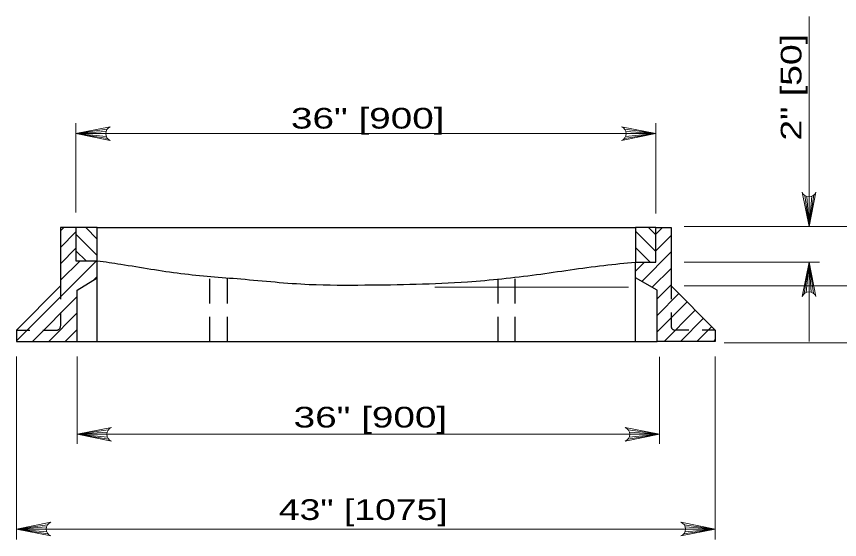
# Model space of a CAD drawing. Extents: x 1083.1 to 1123, y 697.4 to 741.4.
# Drawn here: x 1105.34 to 1111.55, y 704.05 to 708 of the extents above; entities that cross this region are included whole.
import ezdxf

# ---------------------------------------------------------------- set-up
doc = ezdxf.new("R2010")
doc.units = 0
doc.header["$LTSCALE"] = 0.062
doc.linetypes.add('MEDIUM_DASHED', pattern=[4.5, 3, -1.5])
doc.linetypes.add('SHORT_DASHED', pattern=[2.7, 1.5, -1.2])
doc.layers.add('1', color=7, linetype='Continuous', lineweight=13)

msp = doc.modelspace()

# ---------------------------------------------------------------- linework, layer by layer
at = {"layer": '1'}
for p, q in [((1111.32425, 707.99533), (1111.32425, 706.41158)), ((1105.78967, 706.518), (1105.78967, 707.19033)), ((1110.16733, 706.50958), (1110.16733, 707.19033)), ((1106.02425, 707.1445), (1105.78967, 707.11167)), ((1106.01633, 707.12825), (1105.78967, 707.11167)), ((1106.01392, 707.11167), (1105.78967, 707.11167)), ((1106.01808, 707.09058), (1105.78967, 707.11167)), ((1106.027, 707.07533), (1105.78967, 707.11167)), ((1105.78967, 707.11167), (1110.16733, 707.11167)), ((1109.92992, 707.07533), (1110.16733, 707.11167)), ((1109.93275, 707.1445), (1110.16733, 707.11167)), ((1109.93892, 707.09058), (1110.16733, 707.11167)), ((1109.94067, 707.12825), (1110.16733, 707.11167)), ((1109.94308, 707.11167), (1110.16733, 707.11167)), ((1111.29142, 706.64617), (1111.32425, 706.41158)), ((1111.30767, 706.63825), (1111.32425, 706.41158)), ((1111.3605, 706.64892), (1111.32425, 706.41158)), ((1111.34533, 706.64), (1111.32425, 706.41158)), ((1111.32425, 706.63583), (1111.32425, 706.41158)), ((1105.67258, 706.37817), (1105.69808, 706.40367)), ((1105.67258, 706.25392), (1105.78967, 706.371)), ((1105.95067, 706.31642), (1105.86342, 706.40367)), ((1110.16733, 706.22392), (1110.01467, 706.37658)), ((1110.16733, 706.348), (1110.11175, 706.40367)), ((1110.16733, 706.39525), (1110.16733, 706.40367)), ((1110.16733, 706.35233), (1110.21867, 706.40367)), ((1110.16733, 706.39525), (1110.16733, 706.40367)), ((1110.3815, 706.41158), (1112.81892, 706.41158)), ((1105.95067, 706.19233), (1105.78967, 706.35325)), ((1110.16733, 706.22817), (1110.28333, 706.34417)), ((1105.67258, 706.12975), (1105.78967, 706.24683)), ((1110.124, 706.14292), (1110.01467, 706.25233)), ((1105.86542, 706.15333), (1105.78967, 706.229)), ((1110.06075, 705.9975), (1110.28333, 706.22)), ((1105.34017, 705.54908), (1105.94442, 706.15333)), ((1105.67258, 706.00567), (1105.82025, 706.15333)), ((1110.01467, 706.0755), (1110.08208, 706.14292)), ((1111.40292, 706.14292), (1110.3815, 706.14292)), ((1111.288, 705.90558), (1111.32425, 706.14292)), ((1111.30317, 705.91458), (1111.32425, 706.14292)), ((1111.32425, 705.91867), (1111.32425, 706.14292)), ((1111.34083, 705.91625), (1111.32425, 706.14292)), ((1111.35708, 705.90833), (1111.32425, 706.14292)), ((1111.32425, 706.14292), (1111.32425, 705.54517)), ((1110.14025, 705.95275), (1110.28333, 706.09575)), ((1105.92092, 706.00567), (1105.95067, 706.03525)), ((1108.49892, 705.95442), (1109.96083, 705.95442)), ((1110.177, 705.86533), (1110.28333, 705.97158)), ((1105.4605, 705.54517), (1105.79842, 705.88308)), ((1110.177, 705.74117), (1110.34108, 705.90525)), ((1110.177, 705.617), (1110.40317, 705.84308)), ((1105.58467, 705.54517), (1105.79842, 705.759)), ((1110.22925, 705.54517), (1110.46517, 705.781)), ((1110.35358, 705.54517), (1110.52725, 705.719)), ((1105.70883, 705.54517), (1105.79842, 705.63483)), ((1110.47767, 705.54517), (1110.58925, 705.65675)), ((1110.60183, 705.54517), (1110.61625, 705.55958)), ((1112.81892, 705.53383), (1110.68208, 705.53383)), ((1105.34017, 705.43083), (1105.34017, 704.0505)), ((1105.79842, 705.43083), (1105.79842, 704.773)), ((1110.61625, 705.43083), (1110.61625, 704.0505)), ((1110.19408, 705.42825), (1110.19408, 704.773)), ((1106.03308, 704.87717), (1105.79842, 704.84433)), ((1109.9595, 704.87717), (1110.19408, 704.84433)), ((1106.02508, 704.86092), (1105.79842, 704.84433)), ((1106.02267, 704.84433), (1105.79842, 704.84433)), ((1106.02683, 704.82325), (1105.79842, 704.84433)), ((1106.03583, 704.80808), (1105.79842, 704.84433)), ((1105.79842, 704.84433), (1110.19408, 704.84433)), ((1109.95667, 704.80808), (1110.19408, 704.84433)), ((1109.96567, 704.82325), (1110.19408, 704.84433)), ((1109.96742, 704.86092), (1110.19408, 704.84433)), ((1109.96983, 704.84433), (1110.19408, 704.84433)), ((1105.57475, 704.162), (1105.34017, 704.12917)), ((1105.56683, 704.14575), (1105.34017, 704.12917)), ((1105.56442, 704.12917), (1105.34017, 704.12917)), ((1105.56858, 704.10808), (1105.34017, 704.12917)), ((1105.5775, 704.09292), (1105.34017, 704.12917)), ((1105.34017, 704.12917), (1110.61625, 704.12917)), ((1110.37883, 704.09292), (1110.61625, 704.12917)), ((1110.38158, 704.162), (1110.61625, 704.12917)), ((1110.38783, 704.10808), (1110.61625, 704.12917)), ((1110.38958, 704.14575), (1110.61625, 704.12917)), ((1110.392, 704.12917), (1110.61625, 704.12917))]:
    msp.add_line(p, q, dxfattribs=at)
at = {"layer": '1', "lineweight": 25}
for p, q in [((1105.95067, 706.40367), (1110.01467, 706.40367)), ((1105.95067, 705.54267), (1105.95067, 706.02342)), ((1110.01467, 705.54267), (1110.01467, 706.02342)), ((1105.79842, 705.54517), (1110.177, 705.54517))]:
    msp.add_line(p, q, dxfattribs=at)
at = {"layer": '1', "linetype": 'MEDIUM_DASHED', "lineweight": 25}
for p, q in [((1106.79975, 705.54517), (1106.79975, 706.035)), ((1106.93267, 705.54517), (1106.93267, 706.02392)), ((1108.976, 705.54517), (1108.976, 706.02392)), ((1109.10658, 705.54517), (1109.10658, 706.02392))]:
    msp.add_line(p, q, dxfattribs=at)
at = {"layer": '1', "linetype": 'SHORT_DASHED', "lineweight": 25}
for p, q in [((1105.67258, 705.96308), (1105.67258, 705.65908)), ((1110.28333, 705.96308), (1110.28333, 705.65908)), ((1105.34017, 705.62983), (1105.64333, 705.62983)), ((1110.61625, 705.62983), (1110.31258, 705.62983))]:
    msp.add_line(p, q, dxfattribs=at)
at = {"layer": '1'}
for points in [[(1106.04883, 707.05983), (1105.78967, 707.11167), (1106.04883, 707.1635)], [(1109.90817, 707.05983), (1110.16733, 707.11167), (1109.90817, 707.1635)], [(1111.37608, 706.67075), (1111.32425, 706.41158), (1111.27242, 706.67075)], [(1111.27242, 705.88375), (1111.32425, 706.14292), (1111.37608, 705.88375)], [(1112.11092, 705.96308), (1110.81225, 705.96308), (1110.3815, 705.96308)], [(1106.05758, 704.7925), (1105.79842, 704.84433), (1106.05758, 704.89617)], [(1109.93492, 704.7925), (1110.19408, 704.84433), (1109.93492, 704.89617)], [(1105.59933, 704.07733), (1105.34017, 704.12917), (1105.59933, 704.181)], [(1110.35708, 704.07733), (1110.61625, 704.12917), (1110.35708, 704.181)]]:
    msp.add_lwpolyline(points, dxfattribs=at)
at = {"layer": '1', "lineweight": 25}
for points in [[(1105.78967, 706.40367), (1105.67258, 706.40367), (1105.67258, 705.96308), (1105.34017, 705.62983), (1105.34017, 705.54517), (1105.79842, 705.54517), (1105.79842, 705.93208), (1105.95067, 706.02342), (1105.95067, 706.15333)], [(1110.16733, 706.40367), (1110.28333, 706.40367), (1110.28333, 705.96308), (1110.61625, 705.62983), (1110.61625, 705.54517), (1110.177, 705.54517), (1110.177, 705.93208), (1110.01467, 706.02342), (1110.01467, 706.14292)], [(1110.16733, 706.40367), (1110.01467, 706.40367), (1110.01467, 706.14292), (1110.16733, 706.14292), (1110.16733, 706.39525)]]:
    msp.add_lwpolyline(points, dxfattribs=at)
msp.add_lwpolyline([(1105.95067, 706.40367), (1105.78967, 706.40367), (1105.78967, 706.15333), (1105.95067, 706.15333)], close=True, dxfattribs=at)
at = {"layer": '1'}
for centre, start, end in [((1106.06973, 707.1117), 112.08782, 247.91395), ((1109.88726, 707.1117), 292.08605, 67.91218), ((1111.32419, 706.69164), 202.08782, 337.91395), ((1111.3243, 705.86286), 22.08782, 157.91395), ((1106.07852, 704.84438), 112.08782, 247.91395), ((1109.914, 704.84438), 292.08605, 67.91218), ((1105.62023, 704.12925), 112.08782, 247.91395), ((1110.33616, 704.12925), 292.08605, 67.91218)]:
    msp.add_arc(centre, 0.05593, start, end, dxfattribs=at)
at = {"layer": '1', "linetype": 'SHORT_DASHED', "lineweight": 25}
for centre, major_axis, start_param, end_param in [((1105.64332, 705.65909), (0.02927, 0), 4.712389, 6.2831853), ((1110.31258, 705.65909), (-0.02927, 0), 6.2831853, 7.8539816)]:
    msp.add_ellipse(centre, major_axis=major_axis, ratio=0.999895, start_param=start_param, end_param=end_param, dxfattribs=at)
at = {"layer": '1', "lineweight": 25}
msp.add_spline([(1105.95067, 706.15333), (1106.12783, 706.12725), (1106.58208, 706.05733), (1107.03383, 706.01592), (1107.55092, 705.975), (1107.97133, 705.97025), (1108.74475, 705.99492), (1109.26625, 706.04867), (1109.77492, 706.11833), (1110.01467, 706.14292)], degree=3, dxfattribs=at)

# ---------------------------------------------------------------- texts
at = {"layer": '1', "width": 1.35}
msp.add_text('2" [50]', height=0.156, rotation=90, dxfattribs=at).set_placement((1111.26675, 707.05908))
at = {"layer": '1'}
for s, width, p in [('36" [900]', 1.4, (1107.41258, 707.14983)), ('36" [900]', 1.4, (1107.43283, 704.89533)), ('43" [1075]', 1.35, (1107.32117, 704.19808))]:
    msp.add_text(s, height=0.156, dxfattribs=dict(at, width=width)).set_placement(p)

doc.saveas('drawing.dxf')
